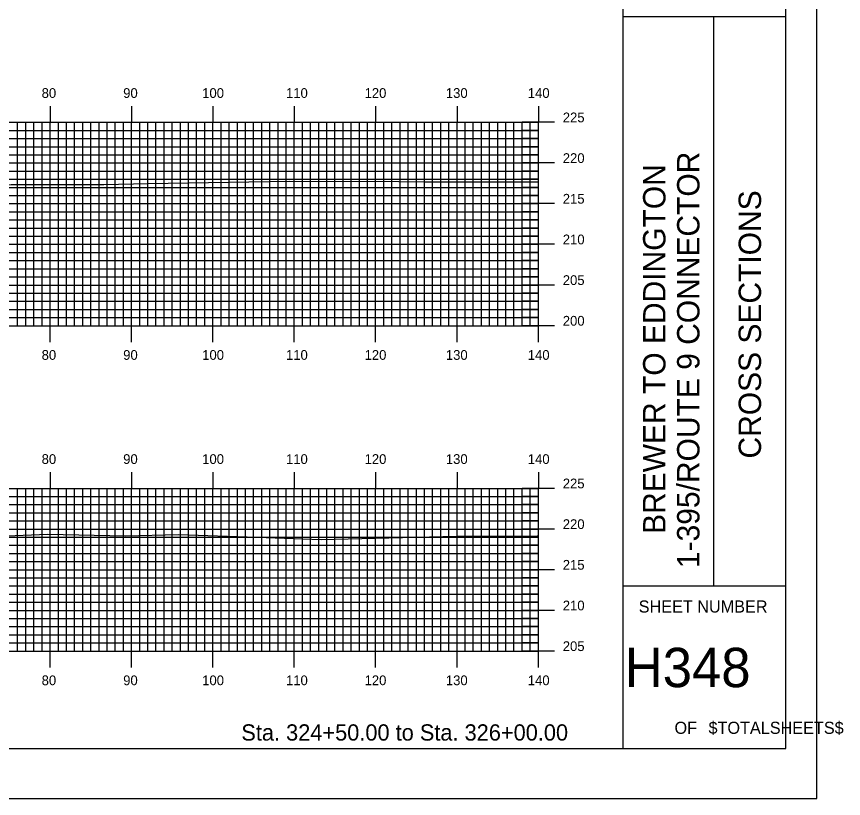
# Model space of a CAD drawing. Extents: x 1821211 to 1821555, y 442591 to 442811.
# Drawn here: x 1821453.1 to 1821554.7, y 442590.5 to 442686.7 of the extents above; entities that cross this region are included whole.
import ezdxf

# ---------------------------------------------------------------- set-up
doc = ezdxf.new("R2010")
doc.units = 0
for name, color, linetype in [('BORDER', 7, 'Continuous'), ('H_V ANNOTATION', 7, 'Continuous'), ('MAJOR', 7, 'Continuous'), ('MINOR', 7, 'Continuous'), ('PLOT BOUNDARY', 7, 'Continuous'), ('S_Roadway_Centerline', 7, 'Continuous')]:
    doc.layers.add(name, color=color, linetype=linetype)

msp = doc.modelspace()

# ---------------------------------------------------------------- linework, layer by layer
at = {"layer": 'BORDER'}
for p, q in [((1821527.63, 442596.67), (1821527.63, 442806.67)), ((1821527.63, 442686.67), (1821547.63, 442686.67)), ((1821538.81, 442616.67), (1821538.81, 442686.67)), ((1821527.63, 442616.67), (1821547.63, 442616.67))]:
    msp.add_line(p, q, dxfattribs=at)
msp.add_lwpolyline([(1821227.63, 442596.67), (1821547.63, 442596.67), (1821547.63, 442806.67), (1821227.63, 442806.67)], close=True, dxfattribs=at)
at = {"layer": 'MAJOR'}
for p, q in [((1821457.23, 442675.67), (1821457.23, 442673.67)), ((1821467.23, 442675.67), (1821467.23, 442673.67)), ((1821477.23, 442675.67), (1821477.23, 442673.67)), ((1821487.23, 442675.67), (1821487.23, 442673.67)), ((1821497.23, 442675.67), (1821497.23, 442673.67)), ((1821507.23, 442675.67), (1821507.23, 442673.67)), ((1821517.23, 442675.67), (1821517.23, 442673.67)), ((1821237.23, 442673.67), (1821517.23, 442673.67)), ((1821237.23, 442673.67), (1821517.23, 442673.67)), ((1821457.23, 442648.67), (1821457.23, 442673.67)), ((1821467.23, 442648.67), (1821467.23, 442673.67)), ((1821477.23, 442648.67), (1821477.23, 442673.67)), ((1821487.23, 442648.67), (1821487.23, 442673.67)), ((1821497.23, 442648.67), (1821497.23, 442673.67)), ((1821507.23, 442648.67), (1821507.23, 442673.67)), ((1821519.23, 442673.67), (1821515.23, 442673.67)), ((1821517.23, 442648.67), (1821517.23, 442673.67)), ((1821517.23, 442648.67), (1821517.23, 442673.67)), ((1821237.23, 442668.67), (1821517.23, 442668.67)), ((1821519.23, 442668.67), (1821515.23, 442668.67)), ((1821237.23, 442663.67), (1821517.23, 442663.67)), ((1821519.23, 442663.67), (1821515.23, 442663.67)), ((1821237.23, 442658.67), (1821517.23, 442658.67)), ((1821519.23, 442658.67), (1821515.23, 442658.67)), ((1821237.23, 442653.67), (1821517.23, 442653.67)), ((1821519.23, 442653.67), (1821515.23, 442653.67)), ((1821237.23, 442648.67), (1821517.23, 442648.67)), ((1821237.23, 442648.67), (1821517.23, 442648.67)), ((1821457.23, 442646.66), (1821457.23, 442648.67)), ((1821467.23, 442646.66), (1821467.23, 442648.67)), ((1821477.23, 442646.66), (1821477.23, 442648.67)), ((1821487.23, 442646.66), (1821487.23, 442648.67)), ((1821497.23, 442646.66), (1821497.23, 442648.67)), ((1821507.23, 442646.66), (1821507.23, 442648.67)), ((1821519.23, 442648.67), (1821515.23, 442648.67)), ((1821517.23, 442646.66), (1821517.23, 442648.67)), ((1821457.23, 442630.67), (1821457.23, 442628.67)), ((1821467.23, 442630.67), (1821467.23, 442628.67)), ((1821477.23, 442630.67), (1821477.23, 442628.67)), ((1821487.23, 442630.67), (1821487.23, 442628.67)), ((1821497.23, 442630.67), (1821497.23, 442628.67)), ((1821507.23, 442630.67), (1821507.23, 442628.67)), ((1821517.23, 442630.67), (1821517.23, 442628.67)), ((1821237.23, 442628.67), (1821517.23, 442628.67)), ((1821237.23, 442628.67), (1821517.23, 442628.67)), ((1821457.23, 442608.67), (1821457.23, 442628.67)), ((1821467.23, 442608.67), (1821467.23, 442628.67)), ((1821477.23, 442608.67), (1821477.23, 442628.67)), ((1821487.23, 442608.67), (1821487.23, 442628.67)), ((1821497.23, 442608.67), (1821497.23, 442628.67)), ((1821507.23, 442608.67), (1821507.23, 442628.67)), ((1821519.23, 442628.67), (1821515.23, 442628.67)), ((1821517.23, 442608.67), (1821517.23, 442628.67)), ((1821517.23, 442608.67), (1821517.23, 442628.67)), ((1821237.23, 442623.67), (1821517.23, 442623.67)), ((1821519.23, 442623.67), (1821515.23, 442623.67)), ((1821237.23, 442618.67), (1821517.23, 442618.67)), ((1821519.23, 442618.67), (1821515.23, 442618.67)), ((1821237.23, 442613.67), (1821517.23, 442613.67)), ((1821519.23, 442613.67), (1821515.23, 442613.67)), ((1821237.23, 442608.67), (1821517.23, 442608.67)), ((1821237.23, 442608.67), (1821517.23, 442608.67)), ((1821457.23, 442606.66), (1821457.23, 442608.67)), ((1821467.23, 442606.66), (1821467.23, 442608.67)), ((1821477.23, 442606.66), (1821477.23, 442608.67)), ((1821487.23, 442606.66), (1821487.23, 442608.67)), ((1821497.23, 442606.66), (1821497.23, 442608.67)), ((1821507.23, 442606.66), (1821507.23, 442608.67)), ((1821519.23, 442608.67), (1821515.23, 442608.67)), ((1821517.23, 442606.66), (1821517.23, 442608.67))]:
    msp.add_line(p, q, dxfattribs=at)
at = {"layer": 'MINOR'}
for p, q in [((1821453.23, 442648.67), (1821453.23, 442673.67)), ((1821454.23, 442648.67), (1821454.23, 442673.67)), ((1821455.23, 442648.67), (1821455.23, 442673.67)), ((1821456.23, 442648.67), (1821456.23, 442673.67)), ((1821458.23, 442648.67), (1821458.23, 442673.67)), ((1821459.23, 442648.67), (1821459.23, 442673.67)), ((1821460.23, 442648.67), (1821460.23, 442673.67)), ((1821461.23, 442648.67), (1821461.23, 442673.67)), ((1821462.23, 442648.67), (1821462.23, 442673.67)), ((1821463.23, 442648.67), (1821463.23, 442673.67)), ((1821464.23, 442648.67), (1821464.23, 442673.67)), ((1821465.23, 442648.67), (1821465.23, 442673.67)), ((1821466.23, 442648.67), (1821466.23, 442673.67)), ((1821468.23, 442648.67), (1821468.23, 442673.67)), ((1821469.23, 442648.67), (1821469.23, 442673.67)), ((1821470.23, 442648.67), (1821470.23, 442673.67)), ((1821471.23, 442648.67), (1821471.23, 442673.67)), ((1821472.23, 442648.67), (1821472.23, 442673.67)), ((1821473.23, 442648.67), (1821473.23, 442673.67)), ((1821474.23, 442648.67), (1821474.23, 442673.67)), ((1821475.23, 442648.67), (1821475.23, 442673.67)), ((1821476.23, 442648.67), (1821476.23, 442673.67)), ((1821478.23, 442648.67), (1821478.23, 442673.67)), ((1821479.23, 442648.67), (1821479.23, 442673.67)), ((1821480.23, 442648.67), (1821480.23, 442673.67)), ((1821481.23, 442648.67), (1821481.23, 442673.67)), ((1821482.23, 442648.67), (1821482.23, 442673.67)), ((1821483.23, 442648.67), (1821483.23, 442673.67)), ((1821484.23, 442648.67), (1821484.23, 442673.67)), ((1821485.23, 442648.67), (1821485.23, 442673.67)), ((1821486.23, 442648.67), (1821486.23, 442673.67)), ((1821488.23, 442648.67), (1821488.23, 442673.67)), ((1821489.23, 442648.67), (1821489.23, 442673.67)), ((1821490.23, 442648.67), (1821490.23, 442673.67)), ((1821491.23, 442648.67), (1821491.23, 442673.67)), ((1821492.23, 442648.67), (1821492.23, 442673.67)), ((1821493.23, 442648.67), (1821493.23, 442673.67)), ((1821494.23, 442648.67), (1821494.23, 442673.67)), ((1821495.23, 442648.67), (1821495.23, 442673.67)), ((1821496.23, 442648.67), (1821496.23, 442673.67)), ((1821498.23, 442648.67), (1821498.23, 442673.67)), ((1821499.23, 442648.67), (1821499.23, 442673.67)), ((1821500.23, 442648.67), (1821500.23, 442673.67)), ((1821501.23, 442648.67), (1821501.23, 442673.67)), ((1821502.23, 442648.67), (1821502.23, 442673.67)), ((1821503.23, 442648.67), (1821503.23, 442673.67)), ((1821504.23, 442648.67), (1821504.23, 442673.67)), ((1821505.23, 442648.67), (1821505.23, 442673.67)), ((1821506.23, 442648.67), (1821506.23, 442673.67)), ((1821508.23, 442648.67), (1821508.23, 442673.67)), ((1821509.23, 442648.67), (1821509.23, 442673.67)), ((1821510.23, 442648.67), (1821510.23, 442673.67)), ((1821511.23, 442648.67), (1821511.23, 442673.67)), ((1821512.23, 442648.67), (1821512.23, 442673.67)), ((1821513.23, 442648.67), (1821513.23, 442673.67)), ((1821514.23, 442648.67), (1821514.23, 442673.67)), ((1821515.23, 442648.67), (1821515.23, 442673.67)), ((1821516.23, 442648.67), (1821516.23, 442673.67)), ((1821237.23, 442672.67), (1821517.23, 442672.67)), ((1821517.23, 442672.67), (1821515.23, 442672.67)), ((1821237.23, 442671.67), (1821517.23, 442671.67)), ((1821517.23, 442671.67), (1821515.23, 442671.67)), ((1821237.23, 442670.67), (1821517.23, 442670.67)), ((1821517.23, 442670.67), (1821515.23, 442670.67)), ((1821237.23, 442669.67), (1821517.23, 442669.67)), ((1821517.23, 442669.67), (1821515.23, 442669.67)), ((1821237.23, 442667.67), (1821517.23, 442667.67)), ((1821517.23, 442667.67), (1821515.23, 442667.67)), ((1821237.23, 442666.67), (1821517.23, 442666.67)), ((1821517.23, 442666.67), (1821515.23, 442666.67)), ((1821237.23, 442665.67), (1821517.23, 442665.67)), ((1821517.23, 442665.67), (1821515.23, 442665.67)), ((1821237.23, 442664.67), (1821517.23, 442664.67)), ((1821517.23, 442664.67), (1821515.23, 442664.67)), ((1821237.23, 442662.67), (1821517.23, 442662.67)), ((1821517.23, 442662.67), (1821515.23, 442662.67)), ((1821237.23, 442661.67), (1821517.23, 442661.67)), ((1821517.23, 442661.67), (1821515.23, 442661.67)), ((1821237.23, 442660.67), (1821517.23, 442660.67)), ((1821517.23, 442660.67), (1821515.23, 442660.67)), ((1821237.23, 442659.67), (1821517.23, 442659.67)), ((1821517.23, 442659.67), (1821515.23, 442659.67)), ((1821237.23, 442657.67), (1821517.23, 442657.67)), ((1821517.23, 442657.67), (1821515.23, 442657.67)), ((1821237.23, 442656.67), (1821517.23, 442656.67)), ((1821517.23, 442656.67), (1821515.23, 442656.67)), ((1821237.23, 442655.67), (1821517.23, 442655.67)), ((1821517.23, 442655.67), (1821515.23, 442655.67)), ((1821237.23, 442654.67), (1821517.23, 442654.67)), ((1821517.23, 442654.67), (1821515.23, 442654.67)), ((1821237.23, 442652.67), (1821517.23, 442652.67)), ((1821517.23, 442652.67), (1821515.23, 442652.67)), ((1821237.23, 442651.67), (1821517.23, 442651.67)), ((1821517.23, 442651.67), (1821515.23, 442651.67)), ((1821237.23, 442650.67), (1821517.23, 442650.67)), ((1821517.23, 442650.67), (1821515.23, 442650.67)), ((1821237.23, 442649.67), (1821517.23, 442649.67)), ((1821517.23, 442649.67), (1821515.23, 442649.67)), ((1821453.23, 442608.67), (1821453.23, 442628.67)), ((1821454.23, 442608.67), (1821454.23, 442628.67)), ((1821455.23, 442608.67), (1821455.23, 442628.67)), ((1821456.23, 442608.67), (1821456.23, 442628.67)), ((1821458.23, 442608.67), (1821458.23, 442628.67)), ((1821459.23, 442608.67), (1821459.23, 442628.67)), ((1821460.23, 442608.67), (1821460.23, 442628.67)), ((1821461.23, 442608.67), (1821461.23, 442628.67)), ((1821462.23, 442608.67), (1821462.23, 442628.67)), ((1821463.23, 442608.67), (1821463.23, 442628.67)), ((1821464.23, 442608.67), (1821464.23, 442628.67)), ((1821465.23, 442608.67), (1821465.23, 442628.67)), ((1821466.23, 442608.67), (1821466.23, 442628.67)), ((1821468.23, 442608.67), (1821468.23, 442628.67)), ((1821469.23, 442608.67), (1821469.23, 442628.67)), ((1821470.23, 442608.67), (1821470.23, 442628.67)), ((1821471.23, 442608.67), (1821471.23, 442628.67)), ((1821472.23, 442608.67), (1821472.23, 442628.67)), ((1821473.23, 442608.67), (1821473.23, 442628.67)), ((1821474.23, 442608.67), (1821474.23, 442628.67)), ((1821475.23, 442608.67), (1821475.23, 442628.67)), ((1821476.23, 442608.67), (1821476.23, 442628.67)), ((1821478.23, 442608.67), (1821478.23, 442628.67)), ((1821479.23, 442608.67), (1821479.23, 442628.67)), ((1821480.23, 442608.67), (1821480.23, 442628.67)), ((1821481.23, 442608.67), (1821481.23, 442628.67)), ((1821482.23, 442608.67), (1821482.23, 442628.67)), ((1821483.23, 442608.67), (1821483.23, 442628.67)), ((1821484.23, 442608.67), (1821484.23, 442628.67)), ((1821485.23, 442608.67), (1821485.23, 442628.67)), ((1821486.23, 442608.67), (1821486.23, 442628.67)), ((1821488.23, 442608.67), (1821488.23, 442628.67)), ((1821489.23, 442608.67), (1821489.23, 442628.67)), ((1821490.23, 442608.67), (1821490.23, 442628.67)), ((1821491.23, 442608.67), (1821491.23, 442628.67)), ((1821492.23, 442608.67), (1821492.23, 442628.67)), ((1821493.23, 442608.67), (1821493.23, 442628.67)), ((1821494.23, 442608.67), (1821494.23, 442628.67)), ((1821495.23, 442608.67), (1821495.23, 442628.67)), ((1821496.23, 442608.67), (1821496.23, 442628.67)), ((1821498.23, 442608.67), (1821498.23, 442628.67)), ((1821499.23, 442608.67), (1821499.23, 442628.67)), ((1821500.23, 442608.67), (1821500.23, 442628.67)), ((1821501.23, 442608.67), (1821501.23, 442628.67)), ((1821502.23, 442608.67), (1821502.23, 442628.67)), ((1821503.23, 442608.67), (1821503.23, 442628.67)), ((1821504.23, 442608.67), (1821504.23, 442628.67)), ((1821505.23, 442608.67), (1821505.23, 442628.67)), ((1821506.23, 442608.67), (1821506.23, 442628.67)), ((1821508.23, 442608.67), (1821508.23, 442628.67)), ((1821509.23, 442608.67), (1821509.23, 442628.67)), ((1821510.23, 442608.67), (1821510.23, 442628.67)), ((1821511.23, 442608.67), (1821511.23, 442628.67)), ((1821512.23, 442608.67), (1821512.23, 442628.67)), ((1821513.23, 442608.67), (1821513.23, 442628.67)), ((1821514.23, 442608.67), (1821514.23, 442628.67)), ((1821515.23, 442608.67), (1821515.23, 442628.67)), ((1821516.23, 442608.67), (1821516.23, 442628.67)), ((1821237.23, 442627.67), (1821517.23, 442627.67)), ((1821517.23, 442627.67), (1821515.23, 442627.67)), ((1821237.23, 442626.67), (1821517.23, 442626.67)), ((1821517.23, 442626.67), (1821515.23, 442626.67)), ((1821237.23, 442625.67), (1821517.23, 442625.67)), ((1821517.23, 442625.67), (1821515.23, 442625.67)), ((1821237.23, 442624.67), (1821517.23, 442624.67)), ((1821517.23, 442624.67), (1821515.23, 442624.67)), ((1821237.23, 442622.67), (1821517.23, 442622.67)), ((1821517.23, 442622.67), (1821515.23, 442622.67)), ((1821237.23, 442621.67), (1821517.23, 442621.67)), ((1821517.23, 442621.67), (1821515.23, 442621.67)), ((1821237.23, 442620.67), (1821517.23, 442620.67)), ((1821517.23, 442620.67), (1821515.23, 442620.67)), ((1821237.23, 442619.67), (1821517.23, 442619.67)), ((1821517.23, 442619.67), (1821515.23, 442619.67)), ((1821237.23, 442617.67), (1821517.23, 442617.67)), ((1821517.23, 442617.67), (1821515.23, 442617.67)), ((1821237.23, 442616.67), (1821517.23, 442616.67)), ((1821517.23, 442616.67), (1821515.23, 442616.67)), ((1821237.23, 442615.67), (1821517.23, 442615.67)), ((1821517.23, 442615.67), (1821515.23, 442615.67)), ((1821237.23, 442614.67), (1821517.23, 442614.67)), ((1821517.23, 442614.67), (1821515.23, 442614.67)), ((1821237.23, 442612.67), (1821517.23, 442612.67)), ((1821517.23, 442612.67), (1821515.23, 442612.67)), ((1821237.23, 442611.67), (1821517.23, 442611.67)), ((1821517.23, 442611.67), (1821515.23, 442611.67)), ((1821237.23, 442610.67), (1821517.23, 442610.67)), ((1821517.23, 442610.67), (1821515.23, 442610.67)), ((1821237.23, 442609.67), (1821517.23, 442609.67)), ((1821517.23, 442609.67), (1821515.23, 442609.67))]:
    msp.add_line(p, q, dxfattribs=at)
at = {"layer": 'PLOT BOUNDARY'}
msp.add_lwpolyline([(1821211.44, 442590.55), (1821551.44, 442590.55), (1821551.44, 442810.55), (1821211.44, 442810.55)], close=True, dxfattribs=at)
at = {"layer": 'S_Roadway_Centerline'}
for points in [[(1821319.61, 442662.84), (1821333.56, 442663.19), (1821350.85, 442663.66), (1821351.69, 442663.68), (1821353.67, 442663.78), (1821385.88, 442665.14), (1821395.98, 442665.86), (1821406.52, 442666.12), (1821418.04, 442665.43), (1821418.63, 442665.43), (1821435.85, 442665.72), (1821444.88, 442665.86), (1821452.44, 442666.04), (1821463.84, 442666.01), (1821469.26, 442666.15), (1821479.16, 442666.31), (1821486.68, 442666.44), (1821500.06, 442666.4), (1821503.32, 442666.34), (1821509.48, 442666.37), (1821517.23, 442666.37)], [(1821320.8, 442620.15), (1821334.26, 442620.5), (1821362.26, 442621.17), (1821365.11, 442621.23), (1821366.24, 442621.25), (1821389.98, 442621.42), (1821402.6, 442621.57), (1821430.07, 442622.08), (1821433.21, 442622.22), (1821435, 442622.15), (1821456.9, 442623.02), (1821466.5, 442622.85), (1821473, 442623.01), (1821482.64, 442622.69), (1821490.54, 442622.39), (1821507.18, 442622.78), (1821517.07, 442622.84), (1821517.23, 442622.83)]]:
    msp.add_lwpolyline(points, dxfattribs=at)

# ---------------------------------------------------------------- texts
at = {"layer": 'BORDER'}
for s, p in [('1-395/ROUTE 9 CONNECTOR', (1821537.03, 442618.87)), ('BREWER TO EDDINGTON', (1821532.85, 442623.07)), ('CROSS SECTIONS', (1821544.6, 442632.34))]:
    msp.add_text(s, height=2.7557, rotation=90, dxfattribs=at).set_placement(p)
for s, height, p in [('SHEET NUMBER', 1.4905, (1821529.56, 442613.4)), ('H348', 4.839, (1821527.84, 442604.23)), ('$TOTALSHEETS$', 1.4905, (1821538.14, 442598.49)), ('OF', 1.491, (1821533.96, 442598.49))]:
    msp.add_text(s, height=height, dxfattribs=at).set_placement(p)
at = {"layer": 'H_V ANNOTATION'}
for s, height, p in [('80', 1.2, (1821456.18, 442676.67)), ('90', 1.2, (1821466.2, 442676.67)), ('100', 1.2, (1821475.91, 442676.67)), ('110', 1.2, (1821486.21, 442676.67)), ('120', 1.2, (1821495.87, 442676.67)), ('130', 1.2, (1821505.86, 442676.67)), ('140', 1.2, (1821515.93, 442676.67)), ('225', 1.2, (1821520.23, 442673.67)), ('220', 1.2, (1821520.23, 442668.67)), ('215', 1.2, (1821520.23, 442663.67)), ('210', 1.2, (1821520.23, 442658.67)), ('205', 1.2, (1821520.23, 442653.67)), ('200', 1.2, (1821520.23, 442648.67)), ('80', 1.2, (1821456.18, 442644.47)), ('90', 1.2, (1821466.2, 442644.47)), ('100', 1.2, (1821475.91, 442644.47)), ('110', 1.2, (1821486.21, 442644.47)), ('120', 1.2, (1821495.87, 442644.47)), ('130', 1.2, (1821505.86, 442644.47)), ('140', 1.2, (1821515.93, 442644.47)), ('80', 1.2, (1821456.18, 442631.67)), ('90', 1.2, (1821466.2, 442631.67)), ('100', 1.2, (1821475.91, 442631.67)), ('110', 1.2, (1821486.21, 442631.67)), ('120', 1.2, (1821495.87, 442631.67)), ('130', 1.2, (1821505.86, 442631.67)), ('140', 1.2, (1821515.93, 442631.67)), ('225', 1.2, (1821520.23, 442628.67)), ('220', 1.2, (1821520.23, 442623.67)), ('215', 1.2, (1821520.23, 442618.67)), ('210', 1.2, (1821520.23, 442613.67)), ('205', 1.2, (1821520.23, 442608.67)), ('80', 1.2, (1821456.18, 442604.47)), ('90', 1.2, (1821466.2, 442604.47)), ('100', 1.2, (1821475.91, 442604.47)), ('110', 1.2, (1821486.21, 442604.47)), ('120', 1.2, (1821495.87, 442604.47)), ('130', 1.2, (1821505.86, 442604.47)), ('140', 1.2, (1821515.93, 442604.47)), ('Sta. 324+50.00 to Sta. 326+00.00', 2.0004, (1821480.72, 442597.66))]:
    msp.add_text(s, height=height, dxfattribs=at).set_placement(p)

doc.saveas('drawing.dxf')
